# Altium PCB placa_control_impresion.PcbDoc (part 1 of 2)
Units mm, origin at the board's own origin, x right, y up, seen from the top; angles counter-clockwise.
Board outline 71.3 x 86.83 mm, 2 copper layers (Top Layer, Bottom Layer); 160 components, 36 nets, 619 pads, 364 vias.
Unrouted connection lines stored in the file: 1.
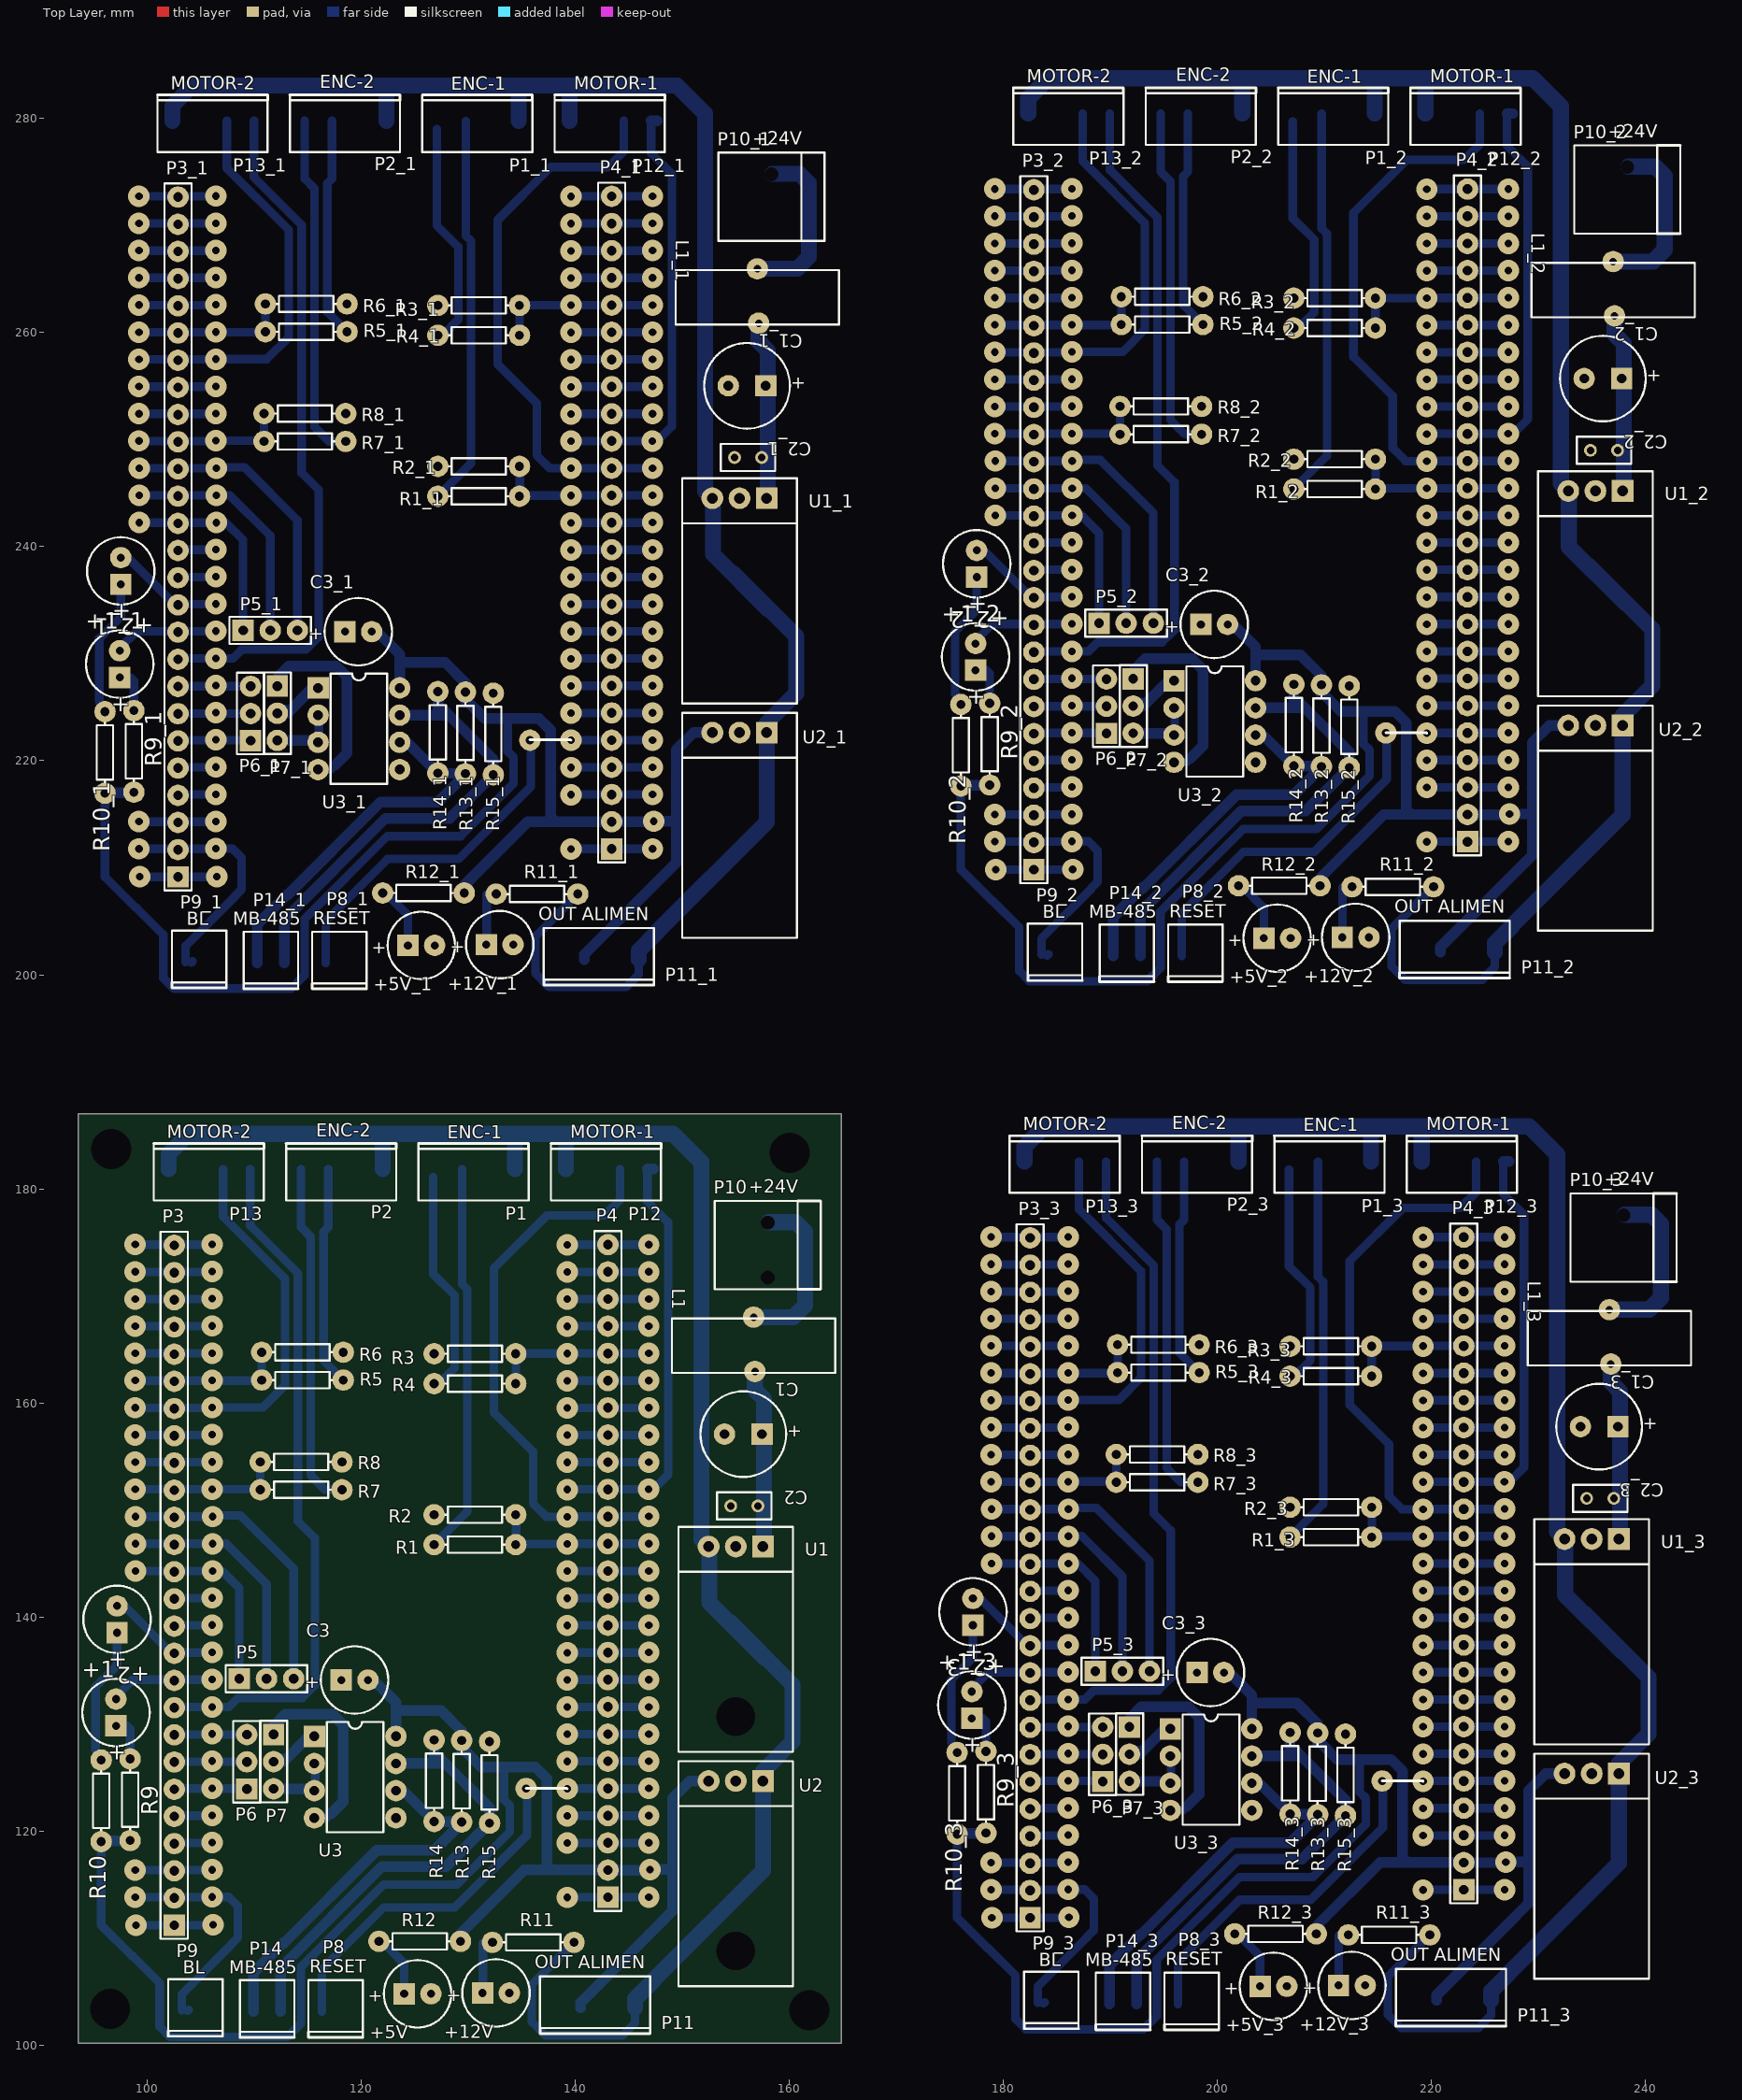
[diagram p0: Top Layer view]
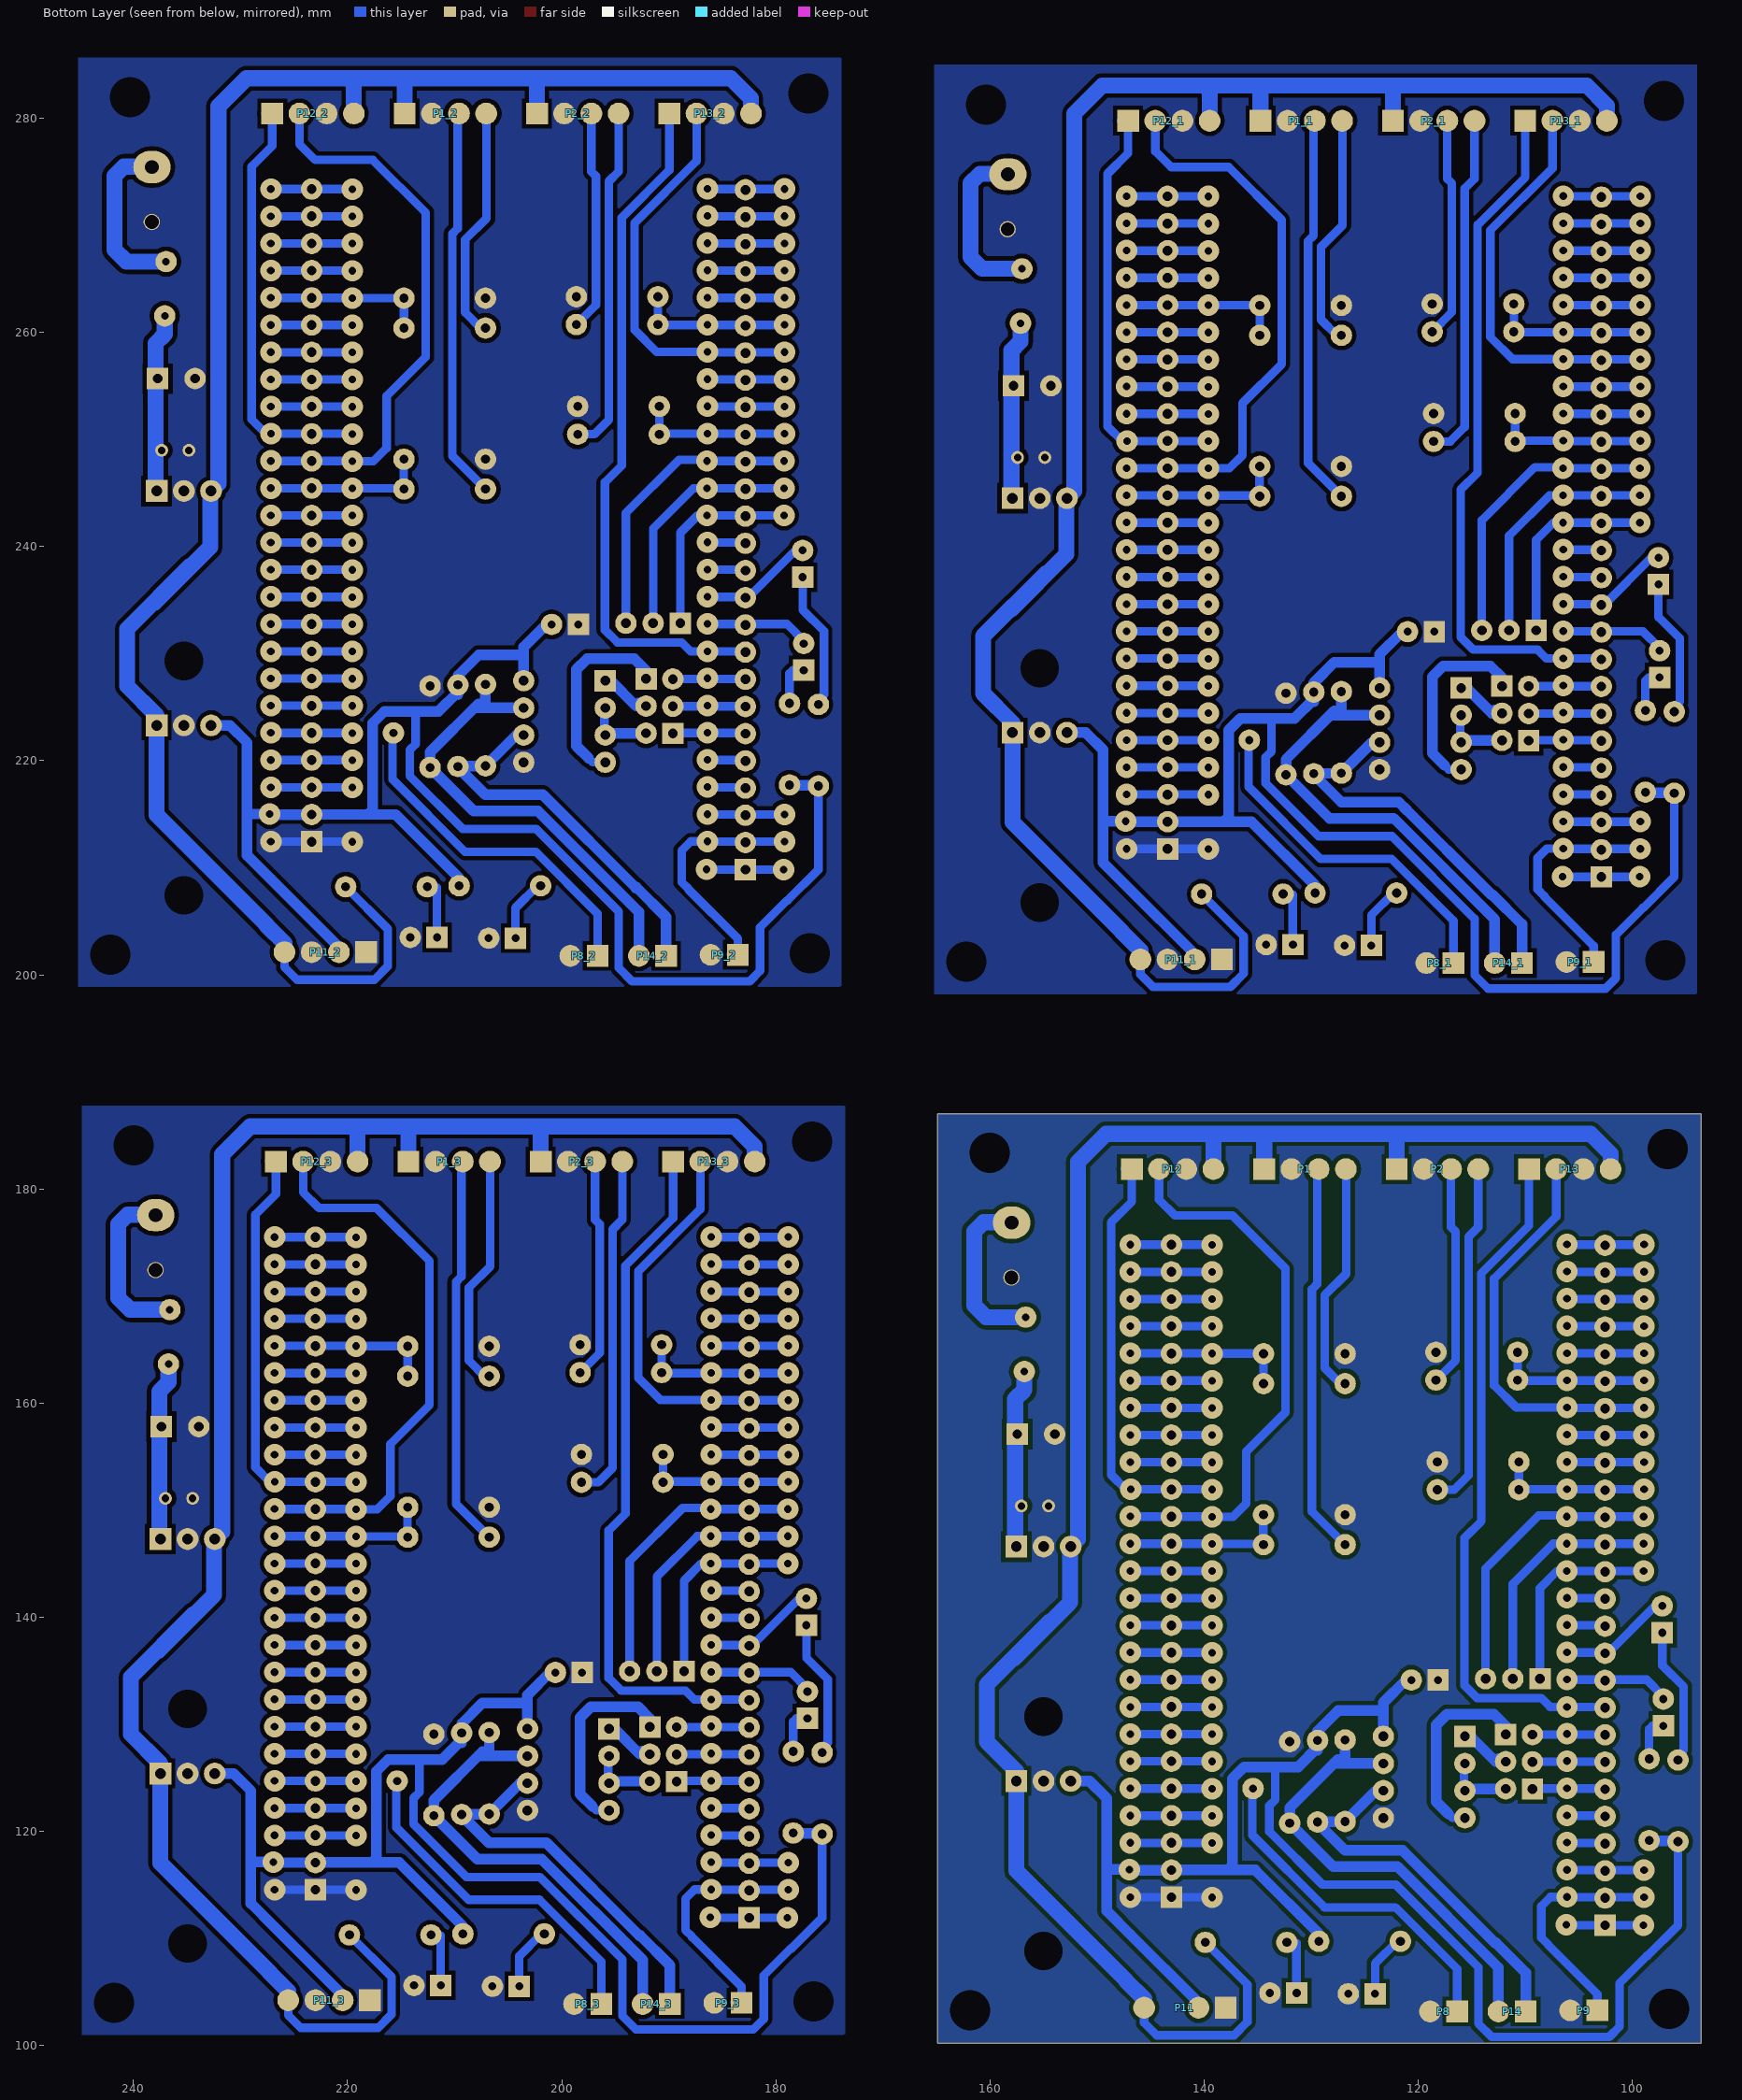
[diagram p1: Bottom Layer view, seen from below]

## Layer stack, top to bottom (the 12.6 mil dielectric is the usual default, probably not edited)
Top Layer: signal copper 0.0356
Dielectric: dielectric 0.32, FR-4, Dk 4.8
Bottom Layer: signal copper 0.0356

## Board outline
93.575,187.025 164.875,187.025 164.875,100.2 93.575,100.2

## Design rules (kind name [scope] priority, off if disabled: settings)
Clearance [All] p1: gap=0.4
ComponentClearance [All] p1: gap=0.254 collisioncheckmode=2 verticalgap=0.254
PlaneConnect [All] p1: planeconnectstyle=Direct reliefexpansion=0.508 reliefentries=4 reliefconductorwidth=0.6 reliefairgap=0.254
PolygonConnect [All] p1: connectstyle=Direct reliefconductorwidth=0.6 reliefentries=4 polygonreliefangle="90 Angle"
RoomDefinition placa_control_esquema_3 [InComponentClass('placa_control_esquema')] p1: confinementstyle=ConfineIn formatcopy=TRUE lockcomponents=FALSE outline 173.525,100.875 244.825,100.875 244.825,187.725 173.525,187.725
RoomDefinition BOARD-ARM_3 [InComponentClass('BOARD-ARM')] p2: confinementstyle=ConfineIn formatcopy=TRUE lockcomponents=FALSE outline 228.213,100.45 173.525,100.45 173.525,180.975 228.213,180.975
RoomDefinition ENCODER_3 [InComponentClass('ENCODER')] p3: confinementstyle=ConfineIn formatcopy=TRUE lockcomponents=FALSE outline 229.275,144.775 229.275,187 179.1,187 179.1,144.775
RoomDefinition INTERFAZ_3 [InComponentClass('INTERFAZ')] p4: confinementstyle=ConfineIn formatcopy=TRUE lockcomponents=FALSE outline 187.05,115.725 219.95,115.725 219.95,141.125 187.05,141.125
RoomDefinition REGULADOR_3 [InComponentClass('REGULADOR')] p5: confinementstyle=ConfineIn formatcopy=TRUE lockcomponents=FALSE outline 200.075,100.875 244.85,100.875 244.85,184.3 200.075,184.3
RoomDefinition placa_control_esquema_2 [InComponentClass('placa_control_esquema')] p6: confinementstyle=ConfineIn formatcopy=TRUE lockcomponents=FALSE outline 173.875,198.775 245.175,198.775 245.175,285.625 173.875,285.625
RoomDefinition BOARD-ARM_2 [InComponentClass('BOARD-ARM')] p7: confinementstyle=ConfineIn formatcopy=TRUE lockcomponents=FALSE outline 228.563,198.35 173.875,198.35 173.875,278.875 228.563,278.875
RoomDefinition ENCODER_2 [InComponentClass('ENCODER')] p8: confinementstyle=ConfineIn formatcopy=TRUE lockcomponents=FALSE outline 229.625,242.675 229.625,284.9 179.45,284.9 179.45,242.675
RoomDefinition INTERFAZ_2 [InComponentClass('INTERFAZ')] p9: confinementstyle=ConfineIn formatcopy=TRUE lockcomponents=FALSE outline 187.4,213.625 220.3,213.625 220.3,239.025 187.4,239.025
RoomDefinition REGULADOR_2 [InComponentClass('REGULADOR')] p10: confinementstyle=ConfineIn formatcopy=TRUE lockcomponents=FALSE outline 200.425,198.775 245.2,198.775 245.2,282.2 200.425,282.2
RoomDefinition placa_control_esquema_1 [InComponentClass('placa_control_esquema')] p11: confinementstyle=ConfineIn formatcopy=TRUE lockcomponents=FALSE outline 93.925,198.1 165.225,198.1 165.225,284.95 93.925,284.95
RoomDefinition BOARD-ARM_1 [InComponentClass('BOARD-ARM')] p12: confinementstyle=ConfineIn formatcopy=TRUE lockcomponents=FALSE outline 148.613,197.675 93.925,197.675 93.925,278.2 148.613,278.2
RoomDefinition ENCODER_1 [InComponentClass('ENCODER')] p13: confinementstyle=ConfineIn formatcopy=TRUE lockcomponents=FALSE outline 149.675,242 149.675,284.225 99.5,284.225 99.5,242
RoomDefinition INTERFAZ_1 [InComponentClass('INTERFAZ')] p14: confinementstyle=ConfineIn formatcopy=TRUE lockcomponents=FALSE outline 107.45,212.95 140.35,212.95 140.35,238.35 107.45,238.35
RoomDefinition REGULADOR_1 [InComponentClass('REGULADOR')] p15: confinementstyle=ConfineIn formatcopy=TRUE lockcomponents=FALSE outline 120.475,198.1 165.25,198.1 165.25,281.525 120.475,281.525
RoomDefinition REGULADOR [InComponentClass('REGULADOR')] p16: confinementstyle=ConfineIn formatcopy=TRUE lockcomponents=FALSE outline 120.125,100.175 164.9,100.175 164.9,183.6 120.125,183.6
RoomDefinition INTERFAZ [InComponentClass('INTERFAZ')] p17: confinementstyle=ConfineIn formatcopy=TRUE lockcomponents=FALSE outline 107.1,115.025 140,115.025 140,140.425 107.1,140.425
RoomDefinition ENCODER [InComponentClass('ENCODER')] p18: confinementstyle=ConfineIn formatcopy=TRUE lockcomponents=FALSE outline 149.325,144.075 149.325,186.3 99.15,186.3 99.15,144.075
RoomDefinition BOARD-ARM [InComponentClass('BOARD-ARM')] p19: confinementstyle=ConfineIn formatcopy=TRUE lockcomponents=FALSE outline 148.263,99.75 93.575,99.75 93.575,180.275 148.263,180.275
RoomDefinition placa_control_esquema [InComponentClass('placa_control_esquema')] p20: confinementstyle=ConfineIn formatcopy=TRUE lockcomponents=FALSE outline 93.575,100.175 164.875,100.175 164.875,187.025 93.575,187.025
RoutingVias [All] p1: holewidth=0.711 width=2 viastyle="Through Hole" minholewidth=0.711 minwidth=1.27 maxholewidth=0.711 maxwidth=2
SolderMaskExpansion [All] p1: expansion=0.102
TestPointUsage [All] p1: valid=0 allowmultiple=FALSE
Testpoint [All] p1: side=15 testpointundercomponent=TRUE minsize=1.016 maxsize=2.54 preferedsize=1.524 minholesize=0 maxholesize=1.016 preferedholesize=0.813 testpointgrid=0.025 style=1023 order=0123456789
Width [All] p1: maxlimit=1.5 minlimit=0.8 preferedwidth=0.8
17 further rules are at their usual default settings.

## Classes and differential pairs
component class placa_control_esquema: P11 P12 P13
component class REGULADOR: +5V +12V C1 C2 L1 P10 R11 R12 U1 U2
component class BOARD-ARM: +1 +2 P3 P4 P5 P6 P7 P8 P9 R9 R10
component class ENCODER: P1 P2 R1 R2 R3 R4 R5 R6 R7 R8
component class INTERFAZ: C3 P14 R13 R14 R15 U3

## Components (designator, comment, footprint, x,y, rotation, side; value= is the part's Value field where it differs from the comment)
+1 "LED2" CAPPR2.5-6.3X5 97.1,131.1 r90 top
+1_1 "LED2" CAPPR2.5-6.3X5 97.45,229.025 r90 top (schematic designator +1)
+1_2 "LED2" CAPPR2.5-6.3X5 177.4,229.7 r90 top (schematic designator +1)
+1_3 "LED2" CAPPR2.5-6.3X5 177.05,131.8 r90 top (schematic designator +1)
+2 "LED2" CAPPR2.5-6.3X5 97.2,139.8 r90 top
+2_1 "LED2" CAPPR2.5-6.3X5 97.55,237.725 r90 top (schematic designator +2)
+2_2 "LED2" CAPPR2.5-6.3X5 177.5,238.4 r90 top (schematic designator +2)
+2_3 "LED2" CAPPR2.5-6.3X5 177.15,140.5 r90 top (schematic designator +2)
+5V "LED2" CAPPR2.5-6.3X5 125.275,104.825 r0 top (schematic designator +4)
+5V_1 "LED2" CAPPR2.5-6.3X5 125.625,202.75 r0 top (schematic designator +4)
+5V_2 "LED2" CAPPR2.5-6.3X5 205.575,203.425 r0 top (schematic designator +4)
+5V_3 "LED2" CAPPR2.5-6.3X5 205.225,105.525 r0 top (schematic designator +4)
+12V "LED2" CAPPR2.5-6.3X5 132.6,104.9 r0 top (schematic designator +3)
+12V_1 "LED2" CAPPR2.5-6.3X5 132.95,202.825 r0 top (schematic designator +3)
+12V_2 "LED2" CAPPR2.5-6.3X5 212.9,203.5 r0 top (schematic designator +3)
+12V_3 "LED2" CAPPR2.5-6.3X5 212.55,105.6 r0 top (schematic designator +3)
C1 "Cap Pol3" CAPPR3.5-8X15 155.7,157.1 r180 top
C1_1 "Cap Pol3" CAPPR3.5-8X15 156.05,255.025 r180 top (schematic designator C1)
C1_2 "Cap Pol3" CAPPR3.5-8X15 236,255.7 r180 top (schematic designator C1)
C1_3 "Cap Pol3" CAPPR3.5-8X15 235.65,157.8 r180 top (schematic designator C1)
C2 "Cap" RAD-0.1 155.8,150.4 r0 top
C2_1 "Cap" RAD-0.1 156.15,248.325 r0 top (schematic designator C2)
C2_2 "Cap" RAD-0.1 236.1,249 r0 top (schematic designator C2)
C2_3 "Cap" RAD-0.1 235.75,151.1 r0 top (schematic designator C2)
C3 "Cap" CAPPR2.5-6.3X5 119.394,134.133 r0 top
C3_1 "Cap" CAPPR2.5-6.3X5 119.744,232.058 r0 top (schematic designator C3)
C3_2 "Cap" CAPPR2.5-6.3X5 199.694,232.733 r0 top (schematic designator C3)
C3_3 "Cap" CAPPR2.5-6.3X5 199.344,134.833 r0 top (schematic designator C3)
L1 "Inductor Iron" bobina_Choque 159.2,167.9 r180 top
L1_1 "Inductor Iron" bobina_Choque 159.55,265.825 r180 top (schematic designator L1)
L1_2 "Inductor Iron" bobina_Choque 239.5,266.5 r180 top (schematic designator L1)
L1_3 "Inductor Iron" bobina_Choque 239.15,168.6 r180 top (schematic designator L1)
P1 "ENC-1" HDR1X5#1 126.758,189.475 r180 top
P1_1 "ENC-1" HDR1X5#1 127.108,287.4 r180 top (schematic designator P1)
P1_2 "ENC-1" HDR1X5#1 207.058,288.075 r180 top (schematic designator P1)
P1_3 "ENC-1" HDR1X5#1 206.708,190.175 r180 top (schematic designator P1)
P2 "ENC-2" HDR1X5#1 114.392,189.475 r180 top
P2_1 "ENC-2" HDR1X5#1 114.742,287.4 r180 top (schematic designator P2)
P2_2 "ENC-2" HDR1X5#1 194.692,288.075 r180 top (schematic designator P2)
P2_3 "ENC-2" HDR1X5#1 194.342,190.175 r180 top (schematic designator P2)
P3 "header26" HDR1x26 107.625,144.25 r90 top
P3_1 "header26" HDR1x26 107.975,242.175 r90 top (schematic designator P3)
P3_2 "header26" HDR1x26 187.925,242.85 r90 top (schematic designator P3)
P3_3 "header26" HDR1x26 187.575,144.95 r90 top (schematic designator P3)
P4 "Header 25" HDR1X25 143.055,113.84 r90 top
P4_1 "Header 25" HDR1X25 143.405,211.765 r90 top (schematic designator P4)
P4_2 "Header 25" HDR1X25 223.355,212.44 r90 top (schematic designator P4)
P4_3 "Header 25" HDR1X25 223.005,114.54 r90 top (schematic designator P4)
P5 "Header 3" HDR1X3 108.625,134.25 r0 top
P5_1 "Header 3" HDR1X3 108.975,232.175 r0 top (schematic designator P5)
P5_2 "Header 3" HDR1X3 188.925,232.85 r0 top (schematic designator P5)
P5_3 "Header 3" HDR1X3 188.575,134.95 r0 top (schematic designator P5)
P6 "Header 3" HDR1X3 109.325,123.95 r90 top
P6_1 "Header 3" HDR1X3 109.675,221.875 r90 top (schematic designator P6)
P6_2 "Header 3" HDR1X3 189.625,222.55 r90 top (schematic designator P6)
P6_3 "Header 3" HDR1X3 189.275,124.65 r90 top (schematic designator P6)
P7 "Header 3" HDR1X3 111.825,129.05 r270 top
P7_1 "Header 3" HDR1X3 112.175,226.975 r270 top (schematic designator P7)
P7_2 "Header 3" HDR1X3 192.125,227.65 r270 top (schematic designator P7)
P7_3 "Header 3" HDR1X3 191.775,129.75 r270 top (schematic designator P7)
P8 "RESET" wf2s 123.975,103.175 r0 top
P8_1 "RESET" wf2s 124.325,201.1 r0 top (schematic designator P8)
P8_2 "RESET" wf2s 204.275,201.775 r0 top (schematic designator P8)
P8_3 "RESET" wf2s 203.925,103.875 r0 top (schematic designator P8)
P9 "BL" wf2s 110.875,103.275 r0 top
P9_1 "BL" wf2s 111.225,201.2 r0 top (schematic designator P9)
P9_2 "BL" wf2s 191.175,201.875 r0 top (schematic designator P9)
P9_3 "BL" wf2s 190.825,103.975 r0 top (schematic designator P9)
P10 "+24V" PWHEADER1X2 157.975,174.95 r90 top
P10_1 "+24V" PWHEADER1X2 158.325,272.875 r90 top (schematic designator P10)
P10_2 "+24V" PWHEADER1X2 238.275,273.55 r90 top (schematic designator P10)
P10_3 "+24V" PWHEADER1X2 237.925,175.65 r90 top (schematic designator P10)
P11 "OUT ALIMEN" HDR1X5#2 145.6,95.9 r0 top
P11_1 "OUT ALIMEN" HDR1X5#1 145.95,193.825 r0 top (schematic designator P11)
P11_2 "OUT ALIMEN" HDR1X5#1 225.9,194.5 r0 top (schematic designator P11)
P11_3 "OUT ALIMEN" HDR1X5#1 225.55,96.6 r0 top (schematic designator P11)
P12 "MOTOR-1" HDR1X5#1 139.125,189.475 r180 top
P12_1 "MOTOR-1" HDR1X5#1 139.475,287.4 r180 top (schematic designator P12)
P12_2 "MOTOR-1" HDR1X5#1 219.425,288.075 r180 top (schematic designator P12)
P12_3 "MOTOR-1" HDR1X5#1 219.075,190.175 r180 top (schematic designator P12)
P13 "MOTOR-2" HDR1X5#1 102.025,189.475 r180 top
P13_1 "MOTOR-2" HDR1X5#1 102.375,287.4 r180 top (schematic designator P13)
P13_2 "MOTOR-2" HDR1X5#1 182.325,288.075 r180 top (schematic designator P13)
P13_3 "MOTOR-2" HDR1X5#1 181.975,190.175 r180 top (schematic designator P13)
P14 "MB-485" wf2s 117.575,103.175 r0 top
P14_1 "MB-485" wf2s 117.925,201.1 r0 top (schematic designator P14)
P14_2 "MB-485" wf2s 197.875,201.775 r0 top (schematic designator P14)
P14_3 "MB-485" wf2s 197.525,103.875 r0 top (schematic designator P14)
R1 "metal film 2%" AXIAL-0.3 130.634,146.777 r180 top
R1_1 "metal film 2%" AXIAL-0.3 130.984,244.702 r180 top (schematic designator R1)
R1_2 "metal film 2%" AXIAL-0.3 210.934,245.377 r180 top (schematic designator R1)
R1_3 "metal film 2%" AXIAL-0.3 210.584,147.477 r180 top (schematic designator R1)
R2 "metal film 2%" AXIAL-0.3 130.634,149.569 r0 top
R2_1 "metal film 2%" AXIAL-0.3 130.984,247.494 r0 top (schematic designator R2)
R2_2 "metal film 2%" AXIAL-0.3 210.934,248.169 r0 top (schematic designator R2)
R2_3 "metal film 2%" AXIAL-0.3 210.584,150.269 r0 top (schematic designator R2)
R3 "metal film 2%" AXIAL-0.3 130.634,161.818 r180 top
R3_1 "metal film 2%" AXIAL-0.3 130.984,259.743 r180 top (schematic designator R3)
R3_2 "metal film 2%" AXIAL-0.3 210.934,260.418 r180 top (schematic designator R3)
R3_3 "metal film 2%" AXIAL-0.3 210.584,162.518 r180 top (schematic designator R3)
R4 "metal film 2%" AXIAL-0.3 130.634,164.61 r0 top
R4_1 "metal film 2%" AXIAL-0.3 130.984,262.535 r0 top (schematic designator R4)
R4_2 "metal film 2%" AXIAL-0.3 210.934,263.21 r0 top (schematic designator R4)
R4_3 "metal film 2%" AXIAL-0.3 210.584,165.31 r0 top (schematic designator R4)
R5 "metal film 2%" AXIAL-0.3 114.525,162.15 r0 top
R5_1 "metal film 2%" AXIAL-0.3 114.875,260.075 r0 top (schematic designator R5)
R5_2 "metal film 2%" AXIAL-0.3 194.825,260.75 r0 top (schematic designator R5)
R5_3 "metal film 2%" AXIAL-0.3 194.475,162.85 r0 top (schematic designator R5)
R6 "metal film 2%" AXIAL-0.3 114.525,164.75 r180 top
R6_1 "metal film 2%" AXIAL-0.3 114.875,262.675 r180 top (schematic designator R6)
R6_2 "metal film 2%" AXIAL-0.3 194.825,263.35 r180 top (schematic designator R6)
R6_3 "metal film 2%" AXIAL-0.3 194.475,165.45 r180 top (schematic designator R6)
R7 "metal film 2%" AXIAL-0.3 114.4,151.9 r0 top
R7_1 "metal film 2%" AXIAL-0.3 114.75,249.825 r0 top (schematic designator R7)
R7_2 "metal film 2%" AXIAL-0.3 194.7,250.5 r0 top (schematic designator R7)
R7_3 "metal film 2%" AXIAL-0.3 194.35,152.6 r0 top (schematic designator R7)
R8 "metal film 2%" AXIAL-0.3 114.4,154.5 r180 top
R8_1 "metal film 2%" AXIAL-0.3 114.75,252.425 r180 top (schematic designator R8)
R8_2 "metal film 2%" AXIAL-0.3 194.7,253.1 r180 top (schematic designator R8)
R8_3 "metal film 2%" AXIAL-0.3 194.35,155.2 r180 top (schematic designator R8)
R9 "Carbon 1/8w 5%" AXIAL-0.3 98.425,122.95 r90 top
R9_1 "Carbon 1/8w 5%" AXIAL-0.3 98.775,220.875 r90 top (schematic designator R9)
R9_2 "Carbon 1/8w 5%" AXIAL-0.3 178.725,221.55 r90 top (schematic designator R9)
R9_3 "Carbon 1/8w 5%" AXIAL-0.3 178.375,123.65 r90 top (schematic designator R9)
R10 "Carbon 1/8w 5%" AXIAL-0.3 95.725,122.85 r90 top
R10_1 "Carbon 1/8w 5%" AXIAL-0.3 96.075,220.775 r90 top (schematic designator R10)
R10_2 "Carbon 1/8w 5%" AXIAL-0.3 176.025,221.45 r90 top (schematic designator R10)
R10_3 "Carbon 1/8w 5%" AXIAL-0.3 175.675,123.55 r90 top (schematic designator R10)
R11 "Carbon 1/8w 5%" AXIAL-0.3 136.075,109.625 r0 top
R11_1 "Carbon 1/8w 5%" AXIAL-0.3 136.425,207.55 r0 top (schematic designator R11)
R11_2 "Carbon 1/8w 5%" AXIAL-0.3 216.375,208.225 r0 top (schematic designator R11)
R11_3 "Carbon 1/8w 5%" AXIAL-0.3 216.025,110.325 r0 top (schematic designator R11)
R12 "Carbon 1/8w 5%" AXIAL-0.3 125.475,109.725 r0 top
R12_1 "Carbon 1/8w 5%" AXIAL-0.3 125.825,207.65 r0 top (schematic designator R12)
R12_2 "Carbon 1/8w 5%" AXIAL-0.3 205.775,208.325 r0 top (schematic designator R12)
R12_3 "Carbon 1/8w 5%" AXIAL-0.3 205.425,110.425 r0 top (schematic designator R12)
R13 "Carbon 1/8w 5%" AXIAL-0.3 129.4,124.675 r90 top
R13_1 "Carbon 1/8w 5%" AXIAL-0.3 129.75,222.6 r90 top (schematic designator R13)
R13_2 "Carbon 1/8w 5%" AXIAL-0.3 209.7,223.275 r90 top (schematic designator R13)
R13_3 "Carbon 1/8w 5%" AXIAL-0.3 209.35,125.375 r90 top (schematic designator R13)
R14 "Carbon 1/8w 5%" AXIAL-0.3 126.826,124.725 r270 top
R14_1 "Carbon 1/8w 5%" AXIAL-0.3 127.176,222.65 r270 top (schematic designator R14)
R14_2 "Carbon 1/8w 5%" AXIAL-0.3 207.126,223.325 r270 top (schematic designator R14)
R14_3 "Carbon 1/8w 5%" AXIAL-0.3 206.776,125.425 r270 top (schematic designator R14)
R15 "Carbon 1/8w 5%" AXIAL-0.3 132,124.575 r270 top
R15_1 "Carbon 1/8w 5%" AXIAL-0.3 132.35,222.5 r270 top (schematic designator R15)
R15_2 "Carbon 1/8w 5%" AXIAL-0.3 212.3,223.175 r270 top (schematic designator R15)
R15_3 "Carbon 1/8w 5%" AXIAL-0.3 211.95,125.275 r270 top (schematic designator R15)
U1 "LM78L12ACZ" T03B 155,146.6 r180 top
U1_1 "LM78L12ACZ" T03B 155.35,244.525 r180 top (schematic designator U1)
U1_2 "LM78L12ACZ" T03B 235.3,245.2 r180 top (schematic designator U1)
U1_3 "LM78L12ACZ" T03B 234.95,147.3 r180 top (schematic designator U1)
U2 "LM78L05ACZ" T03B 155,124.7 r180 top
U2_1 "LM78L05ACZ" T03B 155.35,222.625 r180 top (schematic designator U2)
U2_2 "LM78L05ACZ" T03B 235.3,223.3 r180 top (schematic designator U2)
U2_3 "LM78L05ACZ" T03B 234.95,125.4 r180 top (schematic designator U2)
U3 "SN75176BP" 626-05 119.444,125.065 r270 top
U3_1 "SN75176BP" 626-05 119.794,222.99 r270 top (schematic designator U3)
U3_2 "SN75176BP" 626-05 199.744,223.665 r270 top (schematic designator U3)
U3_3 "SN75176BP" 626-05 199.394,125.765 r270 top (schematic designator U3)

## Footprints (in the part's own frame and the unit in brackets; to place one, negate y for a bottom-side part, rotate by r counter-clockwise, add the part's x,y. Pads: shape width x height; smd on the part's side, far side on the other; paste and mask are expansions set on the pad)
626-05 [mm] "DIP; 8 Leads; Row Spacing 7.62 mm; Pitch 2.54 mm"
  rect 2x2 hole 0.9: 1(-3.81,-3.81)
  round 2 hole 0.9: 2(-1.27,-3.81) 3(1.27,-3.81) 4(3.81,-3.81) 5(3.81,3.81) 6(1.27,3.81) 7(-1.27,3.81) 8(-3.81,3.81)
  silkscreen extent -5.15,-2.65 5.15,2.65
AXIAL-0.3 [mm] "Resistor; 2 Leads"
  round 2 hole 0.85: 1(-3.81,0) 2(3.81,0)
  silkscreen extent -2.77,-0.76 2.77,0.76
bobina_Choque [mm]
  round 2 hole 0.7: 1(2.54,-0.127) 2(2.413,4.953)
  silkscreen extent -5.08,0 10.16,5.08
CAPPR2.5-6.3X5 [mm] "Capacitor, Electrolytic, Radial; Body 6.3 x 5 mm (Dia.xH typ); Pin Spacing 2.5 mm (typ)"
  rect 2x2 hole 0.75: 1(-1.25,0)
  round 2 hole 0.75: 2(1.25,0)
  silkscreen extent -3.15,-3.15 3.15,3.15
CAPPR3.5-8X15 [mm] "Capacitor, Electrolytic, Radial; Body 8 x 15 mm (Dia.xH typ); Pin Spacing 3.5 mm (typ)"
  rect 2x2 hole 0.9: 1(-1.75,0)
  round 2 hole 0.9: 2(1.75,0)
  silkscreen extent -4,-4 4,4
HDR1X3 [mm] "Connector; Header; 3 Position"
  rect 2x2 hole 0.9: 1(0,0)
  round 2 hole 0.9: 2(2.54,0) 3(5.08,0)
  silkscreen extent -1.27,-1.27 6.35,1.27
HDR1X5#1 [mil]
  rect 80x80 smd far side: 1(-300,300)
  round 80 smd far side: 2(-200,300) 3(-100,300) 4(0,300)
  silkscreen extent -350,205 55,415
HDR1X5#2 [mil]
  rect 80x80 smd far side: 1(-300,300)
  round 80 smd far side: 2(-200,300) 4(0,300)
  silkscreen extent -350,205 55,415
HDR1X25 [mm] "Connector; Header; 25 Position"
  rect 2x2 hole 0.9: 1(0,0)
  round 2 hole 0.9: 2(2.54,0) 3(5.08,0) 4(7.62,0) 5(10.16,0) 6(12.7,0) 7(15.24,0) 8(17.78,0) 9(20.32,0) 10(22.86,0) 11(25.4,0) 12(27.94,0) 13(30.48,0) 14(33.02,0) 15(35.56,0) 16(38.1,0) 17(40.64,0) 18(43.18,0) 19(45.72,0) 20(48.26,0) 21(50.8,0) 22(53.34,0) 23(55.88,0) 24(58.42,0) 25(60.96,0)
  silkscreen extent -1.27,-1.27 62.23,1.27
HDR1x26 [mm]
  rect 2x2 hole 0.9: 1(-33.02,5.08)
  round 2 hole 0.9: 2(-30.48,5.08) 3(-27.94,5.08) 4(-25.4,5.08) 5(-22.86,5.08) 6(-20.32,5.08) 7(-17.78,5.08) 8(-15.24,5.08) 9(-12.7,5.08) 10(-10.16,5.08) 11(-7.62,5.08) 12(-5.08,5.08) 13(-2.54,5.08) 14(0,5.08) 15(2.54,5.08) 16(5.08,5.08) 17(7.62,5.08) 18(10.16,5.08) 19(12.7,5.08) 20(15.24,5.08) 21(17.78,5.08) 22(20.32,5.08) 23(22.86,5.08) 24(25.4,5.08) 25(27.94,5.08) 26(30.48,5.08)
  silkscreen extent -34.29,3.81 31.75,6.35
PWHEADER1X2 [mm]
  round 0 / inner round 0 / far side oval 3x3.5 hole 1.3: 2(1.905,0)
  silkscreen extent -4.32,-4.95 3.94,4.95
RAD-0.1 [mm] "Indicating Instrument; 2 Leads"
  round 1.2 hole 0.7: 1(-1.27,0) 2(1.27,0)
  silkscreen extent -2.54,-1.27 2.54,1.27
T03B [mil] "TO, Thru-Hole, Vertical, Heatsink Mounted; 3 In-Line Leads; Pitch 2.54 mm"
  rect 80x80 hole 39.37: 1(-100,0)
  round 80 hole 39.37: 2(0,0) 3(100,0)
  round 80 hole 141.73: 4(0,625)
  silkscreen extent -211,-73 211,755
wf2s [mil]
  rect 80x80 smd far side: 1(-300,0)
  round 80 smd far side: 2(-200,0)
  silkscreen extent -350,-95 -150,115

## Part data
+1 +1_1 +1_2 +1_3 +2 +2_1 +2_2 +2_3 +5V +5V_1 +5V_2 +5V_3 +12V +12V_1 +12V_2 +12V_3: "Typical RED, GREEN, YELLOW, AMBER GaAs LED"
C1 C1_1 C1_2 C1_3: "Polarized Capacitor 35V"
C2 C2_1 C2_2 C2_3 C3 C3_1 C3_2 C3_3: "Capacitor"
L1 L1_1 L1_2 L1_3: "Magnetic-Core Inductor"
P1 P1_1 P1_2 P1_3 P2 P2_1 P2_2 P2_3 P11 P11_1 P11_2 P11_3 P12 P12_1 P12_2 P12_3 P13 P13_1 P13_2 P13_3: library part "Header 4", "Header, 4-Pin"
P3 P3_1 P3_2 P3_3: library part Component_1
P4 P4_1 P4_2 P4_3: "Header, 25-Pin"
P5 P5_1 P5_2 P5_3 P6 P6_1 P6_2 P6_3 P7 P7_1 P7_2 P7_3: "Header, 3-Pin"
P8 P8_1 P8_2 P8_3 P9 P9_1 P9_2 P9_3 P10 P10_1 P10_2 P10_3 P14 P14_1 P14_2 P14_3: library part "Header 2", "Header, 2-Pin"
R1 R1_1 R1_2 R1_3 R2 R2_1 R2_2 R2_3 R3 R3_1 R3_2 R3_3 R4 R4_1 R4_2 R4_3 R5 R5_1 R5_2 R5_3 R6 R6_1 R6_2 R6_3 R7 R7_1 R7_2 R7_3 R8 R8_1 R8_2 R8_3 R9 R9_1 R9_2 R9_3 R10 R10_1 R10_2 R10_3 R11 R11_1 R11_2 R11_3 R12 R12_1 R12_2 R12_3 R13 R13_1 R13_2 R13_3 R14 R14_1 R14_2 R14_3 R15 R15_1 R15_2 R15_3: library part "Res Semi", "Semiconductor Resistor"
U1 U1_1 U1_2 U1_3 U2 U2_1 U2_2 U2_3: "3-Terminal Positive Regulator"
U3 U3_1 U3_2 U3_3: "Differential Bus Transceiver"

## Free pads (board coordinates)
  round 1.524 hole 3.75: 0(96.55,103.425) 0(96.675,183.725) 0(96.9,201.35) 0(97.025,281.65) 0(160.025,183.375) 0(160.375,281.3) 0(161.875,103.3) 0(162.225,201.225) 0(176.5,104.125) 0(176.625,184.425) 0(176.85,202.025) 0(176.975,282.325) 0(239.975,184.075) 0(240.325,281.975) 0(241.825,104) 0(242.175,201.9)
  round 2 hole 0.762: 0(135.425,124) 0(135.775,221.925) 0(215.375,124.7) 0(215.725,222.6)
  round 0 / inner round 0 / far side round 1.524 hole 1.3: 0(158,171.725) 0(158.35,269.65) 0(237.95,172.425) 0(238.3,270.325)

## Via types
v1: diameter 2, hole 0.711, Top Layer to Bottom Layer, 364 vias

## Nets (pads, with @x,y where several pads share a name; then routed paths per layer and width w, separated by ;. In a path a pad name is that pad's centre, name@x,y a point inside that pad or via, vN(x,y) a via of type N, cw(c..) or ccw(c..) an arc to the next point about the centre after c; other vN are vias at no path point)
+5V: C3.2 P4.2 P11.2 R9.1 R10.1 R12.2 R13.2 U2.3 U3.8 | length 152.5
  Bottom Layer w0.8: R10.1@95.725,119.04 95.725,111.225 98.589,108.361 98.639,108.361 101.175,105.825 101.175,101.775 102.15,100.8 113.125,100.8 114.375,102.05 ; 114.375,102.075 114.375,107.307 122.093,115.025 128.95,115.025 133.9,119.975 133.9,122.4 133.35,122.95 133.35,126.018
  Bottom Layer w1: R10.1@95.725,119.04 95.785,119.1 R9.1@98.525,119.1 ; C3.2@121.142,134.133 123.254,132.021 U3.8@123.254,128.875 ; 123.254,131.275 127.475,131.275 R13.2@129.4,129.35 ; R12.2@129.285,110.435 135.23,116.38 P4.2@143.055,116.38 143.06,116.375 v1@146.325,116.375 ; R13.2@129.4,127.575 129.4,127.825 131.207,126.018 136.257,126.018 137.35,124.925 137.35,116.38 ; 137.48,116.38 137.65,116.55 ; P11.2@140.52,103.52 140.52,103.995 146.887,110.362 149.095,112.57 149.095,123.095 150.7,124.7 U2.3@152.46,124.7 ; v1(146.975,116.425) 148.775,116.425
+12V: P1.1 P2.1 P11.4 P12.4 P13.4 R11.2 U1.3 U2.1 | length 176
  Bottom Layer w0.8: R11.2@139.885,109.625 135.95,105.69 135.95,102.2 137.2,100.95 144.425,100.95 145.6,102.125 P11.4@145.6,103.52
  Bottom Layer w1.5: P13.4@102.025,181.855 102.025,183.275 103.9,185.15 149.15,185.15 151.775,182.525 151.775,147.285 152.525,146.535 152.525,141.375 157.74,136.16 ; P2.1@122.012,181.855 122.012,184.637 122.025,184.65 ; P1.1@134.378,181.855 134.378,184.603 134.425,184.65 ; P12.4@139.125,181.855 139.125,184.575 139.2,184.65 ; P11.4@145.6,103.52 145.6,104.35 147.317,106.067 147.317,106.117 157.54,116.34 157.54,125.615 160.3,128.375 160.3,133.7 154.425,139.575
D/~E: P7.3 U3.2 U3.3 | length 6.7
  Bottom Layer w0.8: U3.3@115.634,123.795 115.71,123.87 115.71,126.365 U3.2@115.75,126.325
  Bottom Layer w1: P7.3@111.825,123.97 115.459,123.97 U3.3@115.634,123.795 ; U3.3@115.615,124.27 U3.3@115.71,124.175
D/~E_0: P3.14 P5.1 | length 18.8
  Bottom Layer w0.8: v1(98.94,144.32) 107.005,144.32 108.625,142.7 P5.1@108.625,134.25
  other v1: 106.125,144.32
D/~E_1: P3.6 P6.1 | length 6.9
  Bottom Layer w0.8: P3.6@102.45,124 109.275,124 P6.1@109.325,123.95
  other v1: 106.1,124.025
DRIVER: P7.1 U3.4 | length 18.6
  Bottom Layer w0.8: U3.4@115.634,121.255 116.805,121.255 117.187,121.637
  Bottom Layer w1: P7.1@111.825,129.05 111.825,129.825 112.925,130.925 117.325,130.925 118.325,129.925 118.325,122.775 117.187,121.637
ENC1_FASEZ: P4.21 R3.1 R4.2 | length 15
  Bottom Layer w0.8: R3.1@134.294,162.4 R3.1@134.319,162.425 ; R4.2@134.294,164.575 134.344,164.625 v1(139.25,164.625) ; R4.2@134.319,164.575 R4.2@134.319,164.6 ; R3.1@134.444,161.818 R4.2@134.444,164.61 ; v1@139.555,164.64 v1@146.74,164.64
  other v1: 146.875,164.645
ENC2_FASEZ: P3.17 R7.1 R8.2 | length 14.4
  Bottom Layer w0.8: v1@98.94,151.94 v1@106.125,151.94 ; v1(106.1,151.965) 110.485,151.965 R7.1@110.65,151.8 ; R7.1@110.59,151.9 R8.2@110.59,154.5
  other v1: 98.9,151.95
GND: +5V.2 +12V.2 C1.2 C2.1 C3.1 P1.2 P2.2 P4.1 P8.2 P9.2 P11.1 P12.3 P13.3 pad.0@96.55,103.425 pad.0@96.675,183.725 pad.0@158,171.725 pad.0@160.025,183.375 pad.0@161.875,103.3 R2.1 R4.1 R6.1 R8.1 R15.1 U1.2 U1.4 U2.2 U2.4 U3.5 | length 7.2
  Bottom Layer w0.8: v1@139.555,113.84 v1@146.74,113.84
  other v1: 139.25,113.825 146.875,113.845
IN_B_L: P3.2 P9.1 | length 22
  Bottom Layer w0.8: v1@98.94,113.84 v1@106.125,113.84 ; P9.1@103.255,103.275 103.255,104.78 107.875,109.4 107.875,109.45 108.5,110.075 108.5,113 107.635,113.865 v1(106.1,113.865) ; P9.1@103.795,103.225 P9.1@103.9,103.33
  other v1: 98.9,113.85
IN_SD_1: P4.15 P12.2 | length 51.7
  Bottom Layer w0.8: v1(139.25,149.385) 137.29,149.385 136.06,150.615 136.06,155.465 132.4,159.125 132.4,172.575 137.35,177.525 142.725,177.525 144.205,179.005 P12.2@144.205,181.855 ; v1@139.555,149.4 v1@146.74,149.4
  other v1: 146.875,149.405
IN_SD_2: P3.20 P13.2 | length 37.4
  Bottom Layer w0.8: v1@98.94,159.56 v1@106.125,159.56 ; v1(106.1,159.585) 110.835,159.585 112.9,161.65 112.9,171.625 107.105,177.42 P13.2@107.105,181.855
  other v1: 98.9,159.57
LED_1: +1.2 P3.10 | length 9.9
  Bottom Layer w0.8: +1.2@97.1,132.35 97.1,132.6 98.66,134.16 v1@106.1,134.16
  other v1: 106.1,134.185
LED_2: +2.2 P3.11 | length 10.8
  Bottom Layer w0.8: +2.2@96.9,141.05 97.875,141.05 P3.11@102.225,136.7 ; P3.11@102.5,136.7 v1@106.125,136.7
  other v1: 106.1,136.725
Net+1_1: +1.1 R9.2 | length 4.2
  Bottom Layer w0.8: +1.1@97.1,129.85 98.125,129.85 98.425,129.55 R9.2@98.425,126.76
Net+2_1: +2.1 R10.2 | length 12.9
  Bottom Layer w0.8: R10.2@95.625,126.625 95.625,127.175 95.2,127.6 95.2,133.5 97.2,135.5 +2.1@97.2,138.55
Net+3_1: +12V.1 R11.1 | length 5.1
  Bottom Layer w0.8: +12V.1@131.375,105.1 R11.1@131.375,109.565 ; R11.1@132.265,109.625 R11.1@132.7,109.19
Net+4_1: +5V.1 R12.1 | length 6
  Bottom Layer w0.8: R12.1@121.665,109.725 121.95,109.725 124.025,107.65 +5V.1@124.025,104.825
NetC1_1: C1.1 C2.2 L1.2 U1.1 | length 15.9
  Bottom Layer w1.5: L1.2@156.787,162.147 156.787,161.238 157.64,160.385 U1.1@157.64,146.6
NetL1_1: L1.1 P10.2 | length 15.9
  Bottom Layer w1.5: L1.1@156.66,168.027 160.377,168.027 161.475,169.125 161.475,176.025 160.6,176.9 P10.2@158.075,176.9
NetP1_3: P1.3 R1.2 | length 36.5
  Bottom Layer w0.8: R1.2@126.824,146.777 129.925,149.878 129.925,170.625 129.425,171.125 P1.3@129.425,181.825
NetP1_4: P1.4 R3.2 | length 21.2
  Bottom Layer w0.8: P1.4@126.725,181.1 126.725,172.075 128.725,170.075 128.725,163.275 127.268,161.818 R3.2@126.824,161.818
NetP2_3: P2.3 R5.2 | length 20.6
  Bottom Layer w0.8: P2.3@116.932,181.855 116.932,176.434 116.5,176.002 116.5,163.985 R5.2@118.335,162.15
NetP2_4: P2.4 R7.2 | length 32.5
  Bottom Layer w0.8: P2.4@114.392,181.855 114.392,176.433 115.3,175.525 115.3,153.25 116.65,151.9 R7.2@118.21,151.9
NetP3_21: P3.21 R5.1 R6.2 | length 14.6
  Bottom Layer w0.8: v1@98.8,162.1 110.705,162.1 110.715,162.09 R6.2@110.715,164.75
  other v1: 98.9,162.11 106.1,162.125
NetP4_14: P4.14 R1.1 R2.2 | length 15
  Bottom Layer w0.8: R1.1@134.375,146.875 134.405,146.845 v1(139.25,146.845) v1@139.182,146.777 ; R1.1@134.475,146.9 R2.2@134.475,149.75 ; v1@139.555,146.86 v1@146.74,146.86
  other v1: 146.875,146.865
NetP14_1: P14.1 R13.1 R14.2 U3.6 | length 36.9
  Bottom Layer w1: P14.1@109.955,103.175 109.955,106.805 112.725,109.575 ; 112.775,109.525 121.35,118.1 ; 120.629,117.379 121.475,118.225 126.85,118.225 R13.1@129.6,120.975 ; U3.6@123.946,123.795 R14.2@126.566,121.175 ; R14.2@126.826,120.915 R14.2@126.826,121.301 ; R14.2@126.95,120.95 127.004,120.896 R13.1@129.521,120.896 ; R13.1@129.35,120.915 R13.1@129.4,120.865
NetP14_2: P14.2 R14.1 R15.2 U3.7 | length 44.1
  Bottom Layer w1: P14.2@112.495,103.175 112.495,107.265 121.93,116.7 127.935,116.7 R15.2@132,120.765 ; U3.7@123.254,126.335 127.865,126.335 ; R14.1@126.866,128.575 R14.1@126.826,128.535 126.826,126.724 127.476,126.724 132,122.2 132,120.775 R15.2@131.995,120.77
PWM_1: P4.16 P12.1 | length 39.6
  Bottom Layer w0.8: v1@139.555,151.94 147.315,151.94 148.675,153.3 148.675,176.9 146.745,178.83 P12.1@146.745,181.855
  Bottom Layer w1: P12.1@146.745,181.855 P12.1@147.295,181.855
  other v1: 139.25,151.925 146.85,151.94
PWM_2: P3.9 P13.1 | length 64.8
  Bottom Layer w0.8: P3.9@102.475,131.62 107.67,131.62 108.5,132.45 114.5,132.45 115.675,133.625 115.675,147.4 114.1,148.975 114.1,172.125 109.645,176.58 P13.1@109.645,181.855
  other v1: 106.1,131.62
RECIEVER: P7.2 U3.1 | length 5.1
  Bottom Layer w1: P7.2@111.825,126.51 112.76,126.51 U3.1@115.15,128.9 ; P7.2@112.425,126.8 P7.2@112.525,126.8 ; U3.1@115.05,128.9 U3.1@115.775,128.9
RESET: P4.5 P8.1 pad.0@135.425,124 | length 39.8
  Bottom Layer w0.8: P8.1@116.355,103.175 116.355,107.13 122.125,112.9 128.75,112.9 135.5,119.65 135.5,122.85 pad.0@135.425,124 ; v1@139.555,124 v1@146.74,124
  other v1: 139.25,123.985 146.875,124.005
RX_0: P3.15 P5.2 | length 22.6
  Bottom Layer w0.8: v1(98.94,146.86) 107.39,146.86 111.165,143.085 P5.2@111.165,134.25
  other v1: 106.125,146.86
RX_1: P3.7 P6.2 | length 6.2
  Bottom Layer w0.8: P3.7@102.2,126.49 P6.2@108.325,126.49 ; P6.2@109.275,126.54 P6.2@109.325,126.49
  other v1: 106.1,126.565
TX_0: P3.16 P5.3 | length 27.1
  Bottom Layer w0.8: v1(98.94,149.4) v1(106.125,149.4) ; v1@106.15,149.5 108.75,149.5 113.705,144.545 P5.3@113.705,134.25
TX_1: P3.8 P6.3 | length 6.8
  Bottom Layer w0.8: P3.8@102.475,129.03 P6.3@109.325,129.03
  other v1: 106.1,129.105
